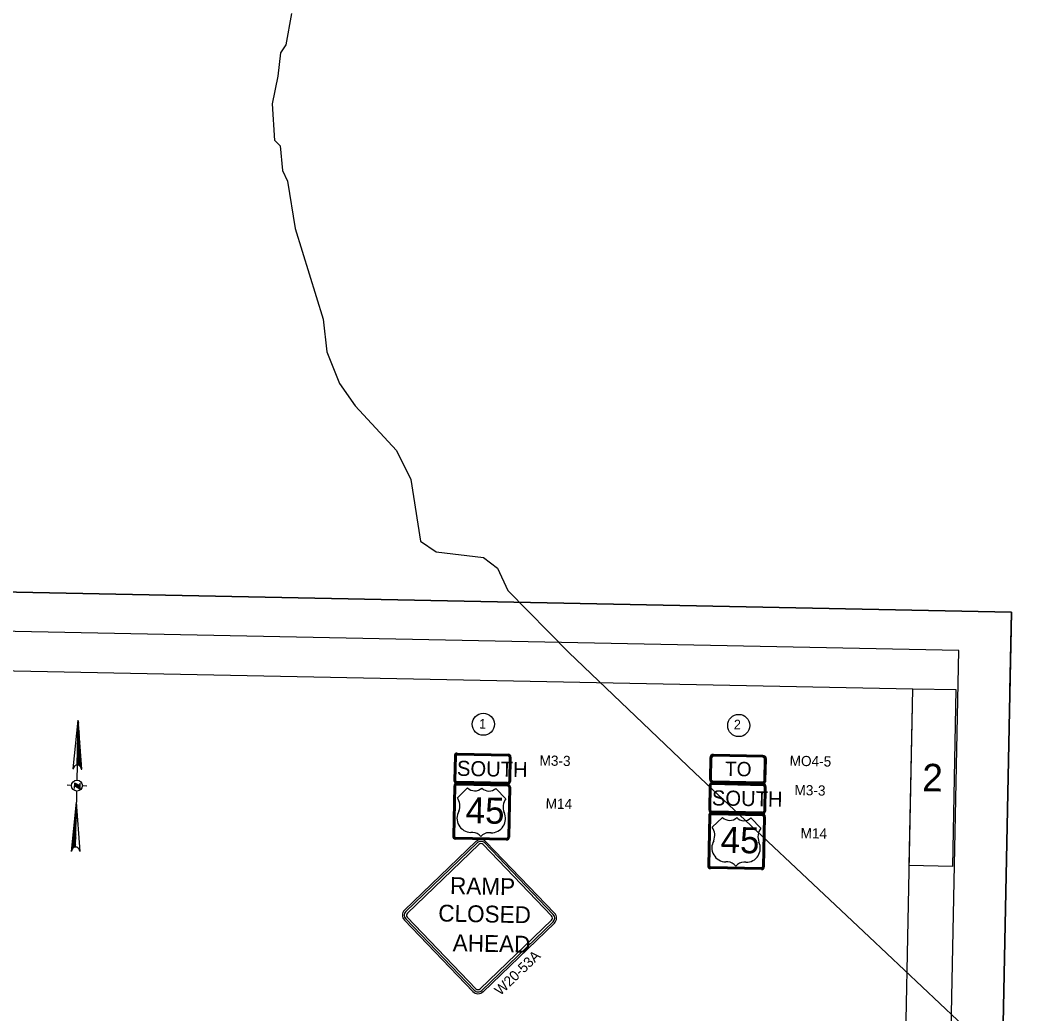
# Model space of a CAD drawing. Extents: x 331323 to 388339, y 121519 to 205315.
# Drawn here: x 365285 to 371668, y 134686 to 141010 of the extents above; entities that cross this region are included whole.
import ezdxf

# ---------------------------------------------------------------- set-up
doc = ezdxf.new("R2010")
doc.units = 0
for name, color, linetype in [('CA-TBLK', 7, 'Continuous'), ('CA-TEXT', 7, 'Continuous'), ('Level 57', 7, 'Continuous'), ('P_RDWY_Text', 7, 'Continuous'), ('P_SGN_Cell', 7, 'Continuous'), ('PLT_Sheet_Border', 7, 'Continuous'), ('PLT_Sheet_Info', 7, 'Continuous')]:
    doc.layers.add(name, color=color, linetype=linetype)

msp = doc.modelspace()

# ---------------------------------------------------------------- linework, layer by layer
at = {"layer": 'CA-TBLK'}
for p, q in [((365623.2, 136245.4), (365654.4, 136554.8)), ((365648.7, 136269.9), (365654.4, 136554.8)), ((365653.7, 136519.8), (365658.8, 136524.7)), ((365653.8, 136524.8), (365658.9, 136529.7)), ((365658.8, 136524.7), (365653.8, 136524.8)), ((365658.9, 136529.7), (365653.9, 136529.8)), ((365659.1, 136539.7), (365654, 136534.8)), ((365654, 136534.8), (365659, 136534.7)), ((365654.1, 136539.8), (365659.1, 136539.7)), ((365654.2, 136544.8), (365659.2, 136544.7)), ((365659.2, 136544.7), (365654.2, 136544.8)), ((365654.3, 136549.8), (365654.3, 136549.8)), ((365678.1, 136244.3), (365654.4, 136554.8)), ((365654.4, 136554.8), (365654.4, 136554.8)), ((365654.4, 136554.8), (365654.4, 136554.8)), ((365652.4, 136454.8), (365662.6, 136464.6)), ((365652.5, 136459.8), (365662.7, 136469.6)), ((365662.6, 136464.6), (365652.5, 136459.8)), ((365662.8, 136474.6), (365652.6, 136464.8)), ((365662.9, 136479.6), (365652.7, 136469.8)), ((365652.7, 136469.8), (365662.8, 136474.6)), ((365652.8, 136474.8), (365662.9, 136479.6)), ((365652.9, 136479.8), (365663.1, 136489.6)), ((365663, 136484.6), (365652.9, 136479.8)), ((365658.1, 136489.7), (365653, 136484.8)), ((365653.1, 136489.8), (365658.2, 136494.7)), ((365658.2, 136494.7), (365653.1, 136489.8)), ((365653.2, 136494.8), (365658.3, 136499.7)), ((365658.4, 136504.7), (365653.3, 136499.8)), ((365653.3, 136499.8), (365658.4, 136504.7)), ((365658.5, 136509.7), (365653.4, 136504.8)), ((365658.6, 136514.7), (365653.5, 136509.8)), ((365653.5, 136509.8), (365658.5, 136509.7)), ((365658.7, 136519.7), (365653.6, 136514.8)), ((365653.6, 136514.8), (365658.6, 136514.7)), ((365666.3, 136399.5), (365651, 136384.8)), ((365651.1, 136389.8), (365666.3, 136399.5)), ((365651.2, 136394.8), (365666.5, 136409.5)), ((365666.4, 136404.5), (365651.2, 136394.8)), ((365651.3, 136399.8), (365666.6, 136414.5)), ((365666.5, 136409.5), (365651.3, 136399.8)), ((365666.6, 136414.5), (365651.4, 136404.8)), ((365666.8, 136424.5), (365651.5, 136409.8)), ((365651.5, 136409.8), (365666.7, 136419.5)), ((365651.6, 136414.8), (365666.8, 136424.5)), ((365661.9, 136429.6), (365651.7, 136419.8)), ((365651.7, 136419.8), (365661.9, 136429.6)), ((365662, 136434.6), (365651.8, 136424.8)), ((365662.1, 136439.6), (365651.9, 136429.8)), ((365651.9, 136429.8), (365662.1, 136439.6)), ((365652, 136434.8), (365662.2, 136444.6)), ((365652.1, 136439.8), (365662.3, 136449.6)), ((365662.2, 136444.6), (365652.1, 136439.8)), ((365662.4, 136454.6), (365652.2, 136444.8)), ((365652.3, 136449.8), (365662.5, 136459.6)), ((365662.5, 136459.6), (365652.4, 136454.8)), ((365670, 136334.4), (365649.6, 136314.8)), ((365670.1, 136339.4), (365649.7, 136319.8)), ((365649.7, 136319.8), (365670, 136334.4)), ((365649.8, 136324.8), (365670.1, 136339.4)), ((365649.9, 136329.8), (365670.3, 136349.4)), ((365670.2, 136344.4), (365649.9, 136329.8)), ((365670.3, 136349.4), (365650, 136334.8)), ((365650.1, 136339.8), (365670.4, 136354.4)), ((365670.4, 136354.4), (365650.1, 136339.8)), ((365670.6, 136364.4), (365650.2, 136344.8)), ((365650.2, 136344.8), (365670.5, 136359.4)), ((365650.3, 136349.8), (365670.6, 136364.4)), ((365665.7, 136369.5), (365650.4, 136354.8)), ((365650.4, 136354.8), (365665.7, 136369.5)), ((365665.8, 136374.5), (365650.5, 136359.8)), ((365650.6, 136364.8), (365665.9, 136379.5)), ((365665.9, 136379.5), (365650.6, 136364.8)), ((365650.7, 136369.8), (365666, 136384.5)), ((365650.8, 136374.8), (365666.1, 136389.5)), ((365666, 136384.5), (365650.8, 136374.8)), ((365666.2, 136394.5), (365650.9, 136379.8)), ((365651, 136384.8), (365666.2, 136394.5)), ((365648.7, 136269.9), (365646.7, 136174.9)), ((365674.1, 136289.3), (365648.7, 136269.9)), ((365648.8, 136274.9), (365674.2, 136294.3)), ((365674.2, 136294.3), (365648.8, 136274.9)), ((365674.4, 136304.3), (365648.9, 136279.9)), ((365648.9, 136279.9), (365674.3, 136299.3)), ((365649, 136284.9), (365674.4, 136304.3)), ((365669.5, 136309.4), (365649.1, 136289.9)), ((365649.1, 136289.9), (365669.5, 136309.4)), ((365669.6, 136314.4), (365649.2, 136294.9)), ((365649.3, 136299.8), (365669.7, 136319.4)), ((365669.7, 136319.4), (365649.3, 136299.8)), ((365649.4, 136304.8), (365669.8, 136324.4)), ((365649.5, 136309.8), (365669.9, 136329.4)), ((365669.8, 136324.4), (365649.5, 136309.8)), ((365653.7, 136269.8), (365674.1, 136289.3)), ((365673.9, 136284.3), (365658.7, 136269.7)), ((365658.7, 136269.7), (365673.8, 136279.4)), ((365673.8, 136279.4), (365663.5, 136264.6)), ((365673.7, 136274.4), (365663.5, 136264.6)), ((365663.5, 136264.6), (365673.7, 136274.4)), ((365668.5, 136264.5), (365673.6, 136269.4)), ((365673.5, 136264.4), (365668.4, 136259.5)), ((365668.4, 136259.5), (365673.5, 136264.4)), ((365673.1, 136244.4), (365678.1, 136244.3)), ((365673.2, 136249.4), (365673.2, 136249.4)), ((365673.2, 136249.4), (365673.2, 136249.4)), ((365673.3, 136254.4), (365673.4, 136259.4)), ((365673.3, 136254.4), (365673.3, 136254.4)), ((365673.4, 136259.4), (365673.4, 136259.4)), ((365611, 136140.6), (365586, 136141.1)), ((365631.3, 136155.2), (365630.6, 136120.2)), ((365641.2, 136150), (365631, 136140.2)), ((365631, 136140.2), (365641.2, 136150)), ((365631, 136140.2), (365646.2, 136149.9)), ((365641.3, 136155), (365631.1, 136145.2)), ((365631.2, 136150.2), (365636.3, 136155.1)), ((365636.3, 136155.1), (365631.2, 136150.2)), ((365631.3, 136155.2), (365631.3, 136155.2)), ((365666, 136139.5), (365631.3, 136155.2)), ((365646.2, 136149.9), (365635.9, 136135.1)), ((365635.9, 136135.1), (365651.1, 136144.8)), ((365651.1, 136144.8), (365640.9, 136135)), ((365640.9, 136135), (365656.1, 136144.7)), ((365645.8, 136129.9), (365656.1, 136144.7)), ((365656.1, 136144.7), (365645.9, 136134.9)), ((365666.3, 136154.5), (365665.6, 136119.5)), ((365631, 136140.2), (365665.6, 136119.5)), ((365645.3, 136104.9), (365643.9, 136034.9)), ((365650.8, 136129.8), (365661, 136139.6)), ((365661, 136139.6), (365650.8, 136129.8)), ((365666, 136139.5), (365650.8, 136129.8)), ((365655.7, 136124.7), (365665.9, 136134.5)), ((365665.9, 136134.5), (365655.7, 136124.7)), ((365660.7, 136124.6), (365665.8, 136129.5)), ((365665.8, 136129.5), (365660.7, 136124.6)), ((365665.6, 136119.5), (365665.7, 136124.5)), ((365681, 136139.2), (365711, 136138.6)), ((365612.6, 135720.5), (365643.9, 136034.9)), ((365638.2, 135750), (365643.9, 136034.9)), ((365643.4, 136009.9), (365643.5, 136014.9)), ((365643.5, 136014.9), (365643.5, 136014.9)), ((365643.6, 136019.9), (365643.6, 136019.9)), ((365643.6, 136019.9), (365643.6, 136019.9)), ((365643.7, 136024.9), (365643.7, 136024.9)), ((365643.8, 136029.9), (365643.8, 136029.9)), ((365643.8, 136029.9), (365643.8, 136029.9)), ((365667.6, 135719.4), (365643.9, 136034.9)), ((365643.9, 136034.9), (365643.9, 136034.9)), ((365637.2, 135950), (365642.1, 135944.9)), ((365642.1, 135944.9), (365637.3, 135955)), ((365637.3, 135955), (365642.2, 135949.9)), ((365642.3, 135954.9), (365637.4, 135960)), ((365637.4, 135960), (365642.3, 135954.9)), ((365642.4, 135959.9), (365637.5, 135965)), ((365637.6, 135970), (365642.4, 135959.9)), ((365642.5, 135964.9), (365637.6, 135970)), ((365642.7, 135974.9), (365637.7, 135975)), ((365637.7, 135975), (365642.6, 135969.9)), ((365637.8, 135980), (365642.7, 135974.9)), ((365642.9, 135984.9), (365642.8, 135979.9)), ((365642.8, 135979.9), (365642.9, 135984.9)), ((365642.9, 135984.9), (365643, 135989.9)), ((365643, 135989.9), (365643.1, 135994.9)), ((365643, 135989.9), (365643, 135989.9)), ((365643.2, 135999.9), (365643.1, 135994.9)), ((365643.3, 136004.9), (365643.2, 135999.9)), ((365643.2, 135999.9), (365643.2, 135999.9)), ((365643.3, 136004.9), (365643.3, 136004.9)), ((365643.4, 136009.9), (365643.4, 136009.9)), ((365631, 135890.1), (365640.8, 135879.9)), ((365640.8, 135879.9), (365631.1, 135895.1)), ((365631.1, 135895.1), (365640.9, 135884.9)), ((365641, 135889.9), (365631.2, 135900.1)), ((365631.2, 135900.1), (365641, 135889.9)), ((365641.1, 135894.9), (365631.3, 135905.1)), ((365631.4, 135910.1), (365641.2, 135899.9)), ((365641.2, 135899.9), (365631.4, 135910.1)), ((365631.5, 135915.1), (365641.3, 135904.9)), ((365641.4, 135909.9), (365631.5, 135915.1)), ((365631.6, 135920.1), (365641.4, 135909.9)), ((365641.5, 135914.9), (365636.7, 135925)), ((365636.7, 135925), (365641.5, 135914.9)), ((365641.6, 135919.9), (365636.8, 135930)), ((365636.9, 135935), (365641.7, 135924.9)), ((365641.7, 135924.9), (365636.9, 135935)), ((365637, 135940), (365641.8, 135929.9)), ((365641.9, 135934.9), (365637, 135940)), ((365637.1, 135945), (365641.9, 135934.9)), ((365642, 135939.9), (365637.1, 135945)), ((365624.7, 135825.2), (365639.3, 135805)), ((365639.4, 135810), (365624.7, 135825.2)), ((365624.8, 135830.2), (365639.5, 135814.9)), ((365639.5, 135814.9), (365624.9, 135835.2)), ((365624.9, 135835.2), (365639.6, 135819.9)), ((365625, 135840.2), (365639.7, 135824.9)), ((365639.7, 135824.9), (365625, 135840.2)), ((365639.8, 135829.9), (365625.1, 135845.2)), ((365625.2, 135850.2), (365639.9, 135834.9)), ((365639.9, 135834.9), (365625.2, 135850.2)), ((365625.3, 135855.2), (365640, 135839.9)), ((365640, 135839.9), (365625.3, 135855.2)), ((365625.4, 135860.2), (365640.1, 135844.9)), ((365640.2, 135849.9), (365625.5, 135865.2)), ((365630.5, 135865.1), (365640.2, 135849.9)), ((365640.3, 135854.9), (365630.6, 135870.1)), ((365630.6, 135870.1), (365640.4, 135859.9)), ((365640.4, 135859.9), (365630.7, 135875.1)), ((365640.6, 135869.9), (365630.8, 135880.1)), ((365630.8, 135880.1), (365640.5, 135864.9)), ((365630.9, 135885.1), (365640.6, 135869.9)), ((365640.7, 135874.9), (365630.9, 135885.1)), ((365618.4, 135760.4), (365628.1, 135745.2)), ((365633.1, 135745.1), (365618.4, 135760.4)), ((365618.5, 135765.4), (365633.2, 135750.1)), ((365638.2, 135750), (365618.5, 135765.4)), ((365618.6, 135770.4), (365638.2, 135750)), ((365638.2, 135750), (365618.7, 135775.4)), ((365618.7, 135775.4), (365638.3, 135755)), ((365638.4, 135760), (365618.8, 135780.4)), ((365618.8, 135780.4), (365638.4, 135760)), ((365638.5, 135765), (365618.9, 135785.4)), ((365619, 135790.4), (365638.5, 135765)), ((365638.6, 135770), (365619, 135790.4)), ((365619.1, 135795.4), (365638.7, 135775)), ((365638.7, 135775), (365619.1, 135795.4)), ((365624.2, 135800.3), (365638.8, 135780)), ((365638.9, 135785), (365624.3, 135805.3)), ((365624.3, 135805.3), (365638.9, 135785)), ((365639, 135790), (365624.4, 135810.3)), ((365624.4, 135810.3), (365639.1, 135795)), ((365639.1, 135795), (365624.5, 135815.3)), ((365624.6, 135820.3), (365639.2, 135800)), ((365639.3, 135805), (365624.6, 135820.3)), ((365612.7, 135725.5), (365612.7, 135725.5)), ((365612.8, 135730.5), (365612.8, 135730.5)), ((365612.8, 135730.5), (365612.8, 135730.5)), ((365612.9, 135735.5), (365617.9, 135735.4)), ((365617.9, 135735.4), (365612.9, 135735.5)), ((365613, 135740.5), (365617.9, 135735.4)), ((365618, 135740.4), (365618.1, 135745.4)), ((365618.1, 135745.4), (365623, 135740.3)), ((365623, 135740.3), (365618.2, 135750.4)), ((365618.2, 135750.4), (365623.1, 135745.3)), ((365628.1, 135745.2), (365618.3, 135755.4))]:
    msp.add_line(p, q, dxfattribs=at)
msp.add_circle((365647.2, 136139.2), 34.8, dxfattribs=at)
for centre, start, end in [((365649.3, 136243.5), 358.84682, 178.84682), ((365649.3, 136243.5), 178.84682, 178.84683), ((365638.8, 135721.8), 358.84682, 178.84682), ((365638.8, 135721.8), 358.84700764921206, 358.8470132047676)]:
    msp.add_arc(centre, 26.1, start, end, dxfattribs=at)
at = {"layer": 'CA-TEXT'}
for centre in [(368233.4, 136529.9), (369859.4, 136521.7)]:
    msp.add_circle(centre, 70.4, dxfattribs=at)
at = {"layer": 'Level 57'}
for points in [[(366907.1, 140244.2), (366892.6, 140477.7), (366927.6, 140652.4), (366945.6, 140802.2), (366979.4, 140851.9), (367014.6, 141051.6)], [(366907.1, 140244.2), (366940.2, 140210.6), (366955.4, 140052.1), (366988.1, 139985.1), (367035.4, 139684.7), (367213.5, 139108.1), (367236.6, 138899.5), (367318.2, 138698.8), (367417, 138556.2), (367681.2, 138270.5), (367771.2, 138086.3), (367834.3, 137694.1), (367933.8, 137626.5), (368233.7, 137590.5), (368324.8, 137523), (368390.2, 137380.7), (368778.5, 136985.5), (369580.4, 136219.9), (370688.4, 135176.5), (371812.8, 134116.3), (371829.2, 134082.8)]]:
    msp.add_lwpolyline(points, dxfattribs=at)
at = {"layer": 'P_RDWY_Text'}
msp.add_lwpolyline([(354597.6, 137585.1), (371594.2, 137242.8), (371372.7, 126245), (354376.1, 126587.3)], close=True, dxfattribs=at)
at = {"layer": 'P_SGN_Cell'}
for p, q in [((368067.6, 136346), (368391.7, 136339.5)), ((368067.6, 136335.5), (368391.5, 136329)), ((368067.7, 136341.5), (368391.7, 136335)), ((368049.5, 136328.4), (368046.3, 136172.4)), ((368054, 136328.3), (368050.8, 136172.3)), ((368060, 136328.2), (368056.8, 136172.2)), ((368398.9, 136321.4), (368395.7, 136165.4)), ((368404.9, 136321.2), (368401.7, 136165.3)), ((368409.4, 136321.1), (368406.2, 136165.2)), ((368063.8, 136154.1), (368388, 136147.5)), ((368387.9, 136147.5), (368063.9, 136154.1)), ((368063.9, 136143.6), (368387.8, 136137)), ((368388, 136152), (368064, 136158.6)), ((368064, 136149.6), (368387.9, 136143)), ((368388.1, 136158), (368064.2, 136164.6)), ((369689.9, 136157.9), (370014.1, 136151.4)), ((369690, 136147.4), (370013.9, 136140.9)), ((369690.1, 136153.4), (370014, 136146.9)), ((368045.7, 136136.4), (368039.3, 135817.5)), ((368050.2, 136136.3), (368043.8, 135817.4)), ((368056.2, 136136.2), (368049.8, 135817.3)), ((368068.2, 136062.2), (368133.8, 136125.2)), ((368116.1, 136140.4), (368116.1, 136140.4)), ((368313.8, 136121.6), (368376.8, 136056)), ((368395.1, 136129.4), (368388.7, 135810.5)), ((368401.1, 136129.3), (368394.7, 135810.4)), ((368405.6, 136129.2), (368399.2, 135810.3)), ((369671.8, 136140.3), (369668.7, 135984.3)), ((369676.3, 136140.2), (369673.2, 135984.2)), ((369682.3, 136140.1), (369679.2, 135984.1)), ((370021.3, 136133.2), (370018.1, 135977.3)), ((370027.3, 136133.1), (370024.1, 135977.1)), ((370031.8, 136133), (370028.6, 135977.1)), ((369686.2, 135966), (370010.4, 135959.4)), ((369686.2, 135955.4), (370010.2, 135948.9)), ((370010.3, 135959.4), (369686.3, 135965.9)), ((370010.3, 135963.9), (369686.4, 135970.4)), ((369686.4, 135961.4), (370010.3, 135954.9)), ((370010.5, 135969.9), (369686.5, 135976.4)), ((369738.5, 135952.3), (369738.5, 135952.3)), ((369668.1, 135948.3), (369661.7, 135629.4)), ((369672.6, 135948.2), (369666.2, 135629.3)), ((369678.6, 135948.1), (369672.2, 135629.2)), ((369690.6, 135874.1), (369756.2, 135937.1)), ((369936.2, 135933.5), (369999.2, 135867.9)), ((370017.5, 135941.3), (370011.1, 135622.4)), ((370023.5, 135941.2), (370017.1, 135622.3)), ((370028, 135941.1), (370021.6, 135622.2)), ((368166.7, 135841.6), (368153.8, 135841.8)), ((368282.4, 135839.2), (368269.5, 135839.5)), ((368380.9, 135792.7), (368056.9, 135799.2)), ((368380.9, 135797.2), (368057, 135803.7)), ((368381.1, 135803.2), (368057.1, 135809.7)), ((369789.1, 135653.5), (369776.2, 135653.7)), ((369904.8, 135651.1), (369891.9, 135651.4)), ((370003.2, 135604.5), (369679.3, 135611.1)), ((370003.3, 135609), (369679.4, 135615.6)), ((370003.4, 135615), (369679.5, 135621.6))]:
    msp.add_line(p, q, dxfattribs=at)
for points in [[(370013, 136325.8), (369698.1, 136332.2)], [(370013.1, 136331.4), (369698.2, 136337.8)], [(369675.2, 136315.7), (369672.5, 136180.8)], [(369680.9, 136315.6), (369678.1, 136180.7)], [(369686.5, 136315.5), (369683.8, 136180.5)], [(370012.9, 136320.2), (369698, 136326.5)], [(370021.2, 136173.7), (370023.9, 136308.7)], [(370026.8, 136173.6), (370029.5, 136308.6)], [(370032.5, 136173.5), (370035.2, 136308.5)], [(369694.6, 136157.8), (370009.5, 136151.5)], [(369694.7, 136163.4), (370009.6, 136157.1)], [(369694.8, 136169.1), (370009.7, 136162.7)], [(368186.8, 135783.4), (367732.5, 135347)], [(368194.7, 135775.1), (367740.4, 135338.7)], [(368204.6, 135764.8), (367750.3, 135328.4)], [(368668.3, 135309.9), (368231.9, 135764.3)], [(368678.6, 135319.8), (368242.2, 135774.2)], [(368686.9, 135327.7), (368250.4, 135782.1)], [(367731.2, 135283.3), (368167.6, 134829)], [(367739.4, 135291.2), (368175.8, 134836.9)], [(367749.7, 135301.1), (368186.1, 134846.8)], [(368213.8, 134846.6), (368668, 135282.9)], [(368223.7, 134836.3), (368677.9, 135272.5)], [(368231.6, 134828), (368685.8, 135264.3)]]:
    msp.add_lwpolyline(points, dxfattribs=at)
for centre, radius, start, end in [((368067.4, 136328), 18, 89.61188, 178.84622), ((368067.4, 136328), 13.5, 88.84622, 178.84622), ((368067.4, 136328), 7.5, 88.84622, 178.84622), ((368391.4, 136321.5), 18, 358.84622, 88.84622), ((368391.4, 136321.5), 13.5, 358.84622, 88.84622), ((369697.7, 136315.3), 22.5, 88.84622, 178.84622), ((369697.7, 136315.3), 16.9, 88.84622, 178.84622), ((368391.4, 136321.5), 7.5, 358.84622, 88.84622), ((369697.7, 136315.3), 11.2, 88.84622, 178.84622), ((370012.7, 136308.9), 11.2, 358.84622, 88.84622), ((370012.7, 136308.9), 16.9, 358.84622, 88.84622), ((370012.7, 136308.9), 22.5, 358.84622, 88.84622), ((368063.7, 136136.1), 18, 89.61188, 178.84622), ((368064.3, 136172.1), 18, 178.84622, 268.84622), ((368063.7, 136136.1), 13.5, 88.84622, 178.84622), ((368064.3, 136172.1), 13.5, 178.84622, 268.84622), ((368063.7, 136136.1), 7.5, 88.84622, 178.84622), ((368064.3, 136172.1), 7.5, 178.84622, 268.84622), ((368388.2, 136165.5), 18, 268.84622, 358.84622), ((368387.6, 136129.5), 13.5, 358.84622, 88.84622), ((368388.2, 136165.5), 13.5, 268.84622, 358.84622), ((368387.6, 136129.5), 18, 358.84622, 88.84622), ((368388.2, 136165.5), 7.5, 268.84622, 358.84622), ((369689.8, 136139.9), 18, 89.61188, 178.84622), ((369695, 136180.3), 22.5, 178.84622, 268.84622), ((369689.8, 136139.9), 13.5, 88.84622, 178.84622), ((369695, 136180.3), 16.9, 178.84622, 268.84622), ((369689.8, 136139.9), 7.5, 88.84622, 178.84622), ((369695, 136180.3), 11.2, 178.84622, 268.84622), ((370010, 136174), 22.5, 268.84622, 358.84622), ((370010, 136174), 16.9, 268.84622, 358.84622), ((370010, 136174), 11.2, 268.84622, 358.84622), ((370013.8, 136133.4), 7.5, 358.84622, 88.84622), ((370013.8, 136133.4), 13.5, 358.84622, 88.84622), ((370013.8, 136133.4), 18, 358.84622, 88.84622), ((368179.7, 136170.2), 64.3, 224.41906, 313.27339), ((368269.7, 136168.4), 64.3, 224.41906, 313.27339), ((368387.6, 136129.5), 7.5, 358.84622, 88.84622), ((367994.3, 136010.8), 90, 337.71592, 34.79823), ((368448.8, 136002), 90, 143.11428, 201.9873), ((368155.6, 135931.8), 90, 150.09813, 268.84629), ((368284.2, 135929.2), 90, 268.84616, 25.69277), ((369686.1, 135948), 18, 89.61188, 178.84622), ((369686.7, 135983.9), 18, 178.84622, 268.84622), ((369686.1, 135948), 13.5, 88.84622, 178.84622), ((369686.7, 135983.9), 13.5, 178.84622, 268.84622), ((369686.1, 135948), 7.5, 88.84622, 178.84622), ((369686.7, 135983.9), 7.5, 178.84622, 268.84622), ((370010.6, 135977.4), 13.5, 268.84622, 358.84622), ((370010.6, 135977.4), 18, 268.84622, 358.84622), ((370010, 135941.4), 13.5, 358.84622, 88.84622), ((370010, 135941.4), 18, 358.84622, 88.84622), ((370010.6, 135977.4), 7.5, 268.84622, 358.84622), ((369802.1, 135982.1), 64.3, 224.41906, 313.27339), ((369892.1, 135980.3), 64.3, 224.41906, 313.27339), ((370010, 135941.4), 7.5, 358.84622, 88.84622), ((368165, 135776.5), 65.1, 36.05841, 88.50393), ((368268.6, 135774.4), 65.1, 89.18852, 141.63404), ((369616.7, 135822.7), 90, 337.71592, 34.79823), ((370071.2, 135813.9), 90, 143.11428, 201.9873), ((368057.3, 135817.2), 18, 178.84622, 268.84622), ((368057.3, 135817.2), 13.5, 178.84622, 268.84622), ((368057.3, 135817.2), 7.5, 178.84622, 268.84622), ((368218, 135750.9), 45, 43.84433, 133.84622), ((368218, 135750.9), 33.6, 43.84433, 133.84622), ((368218, 135750.9), 19.3, 43.84433, 133.84622), ((368381.2, 135810.7), 13.5, 268.84622, 358.84622), ((368381.2, 135810.7), 18, 268.84622, 358.84622), ((368381.2, 135810.7), 7.5, 268.84622, 358.84622), ((369778, 135743.7), 90, 150.09813, 268.84629), ((369906.6, 135741.1), 90, 268.84616, 25.69277), ((369787.4, 135588.4), 65.1, 36.05841, 88.50393), ((369891, 135586.3), 65.1, 89.18852, 141.63404), ((369679.7, 135629.1), 18, 178.84622, 268.84622), ((369679.7, 135629.1), 13.5, 178.84622, 268.84622), ((369679.7, 135629.1), 7.5, 178.84622, 268.84622), ((370003.6, 135622.5), 18, 268.84622, 358.84622), ((370003.6, 135622.5), 13.5, 268.84622, 358.84622), ((370003.6, 135622.5), 7.5, 268.84622, 358.84622), ((367763.6, 135314.5), 45, 133.84622, 223.84622), ((367763.6, 135314.5), 33.6, 133.84622, 223.84622), ((367763.6, 135314.5), 19.3, 133.84622, 223.84622), ((368654.4, 135296.6), 33.6, 313.84622, 43.84622), ((368654.4, 135296.6), 45, 313.84622, 43.84622), ((368654.4, 135296.6), 19.3, 313.84622, 43.84622), ((368200, 134860.2), 45, 223.85344, 314.49709), ((368200, 134860.2), 33.6, 223.85344, 314.49709), ((368200, 134860.2), 19.3, 223.85344, 314.49709)]:
    msp.add_arc(centre, radius, start, end, dxfattribs=at)
at = {"layer": 'PLT_Sheet_Border'}
for points in [[(354376.1, 126587.3), (371372.7, 126245), (371594.2, 137242.8), (354597.6, 137585.1)], [(354501.1, 126834.8), (371047.8, 126501.6), (371259.2, 136999.5), (354712.6, 137332.7)]]:
    msp.add_lwpolyline(points, close=True, dxfattribs=at)
at = {"layer": 'PLT_Sheet_Info'}
for p, q in [((371094.3, 137252.8), (371594.2, 137242.8)), ((371584.1, 136742.9), (371594.2, 137242.8)), ((355219.9, 137072.4), (370966.7, 136755.3)), ((370765.4, 126757.3), (370966.7, 136755.3))]:
    msp.add_line(p, q, dxfattribs=at)
msp.add_lwpolyline([(370966.7, 136755.3), (371241.7, 136749.8), (371219, 135625), (370944.1, 135630.5)], close=True, dxfattribs=at)

# ---------------------------------------------------------------- texts
at = {"layer": 'CA-TEXT'}
for s, p in [('1', (368206.4, 136502.8)), ('2', (369827.5, 136498.4))]:
    msp.add_text(s, height=60, rotation=358.84682, dxfattribs=at).set_placement(p)
at = {"layer": 'P_SGN_Cell'}
for s, height, rotation, p in [('SOUTH', 96, 358.84622, (368065.2, 136201.8)), ('M3-3', 64.8, 358.84622, (368590.8, 136267.3)), ('TO', 91.2, 358.84622, (369770.4, 136201.2)), ('MO4-5', 64.8, 358.84622, (370182.4, 136265.4)), ('M3-3', 64.8, 358.84622, (370213.2, 136079.2)), ('SOUTH', 96, 358.84622, (369687.6, 136013.7)), ('45', 165.6, 358.84622, (368120.3, 135900.5)), ('M14', 64.8, 358.84622, (368629.7, 135993)), ('45', 165.6, 358.84622, (369742.6, 135712.4)), ('M14', 64.8, 358.84622, (370252, 135804.9)), ('RAMP', 107.14, 358.84622, (368020.9, 135450)), ('CLOSED', 107.14, 358.84622, (367946.1, 135275)), ('AHEAD', 107.14, 358.84622, (368038.3, 135085.7)), ('W20-53A', 64.8, 43.84682, (368341.8, 134799.5))]:
    msp.add_text(s, height=height, rotation=rotation, dxfattribs=at).set_placement(p)
at = {"layer": 'PLT_Sheet_Info'}
msp.add_text('2', height=175, rotation=358.84622, dxfattribs=at).set_placement((371025.7, 136104))

doc.saveas('drawing.dxf')
